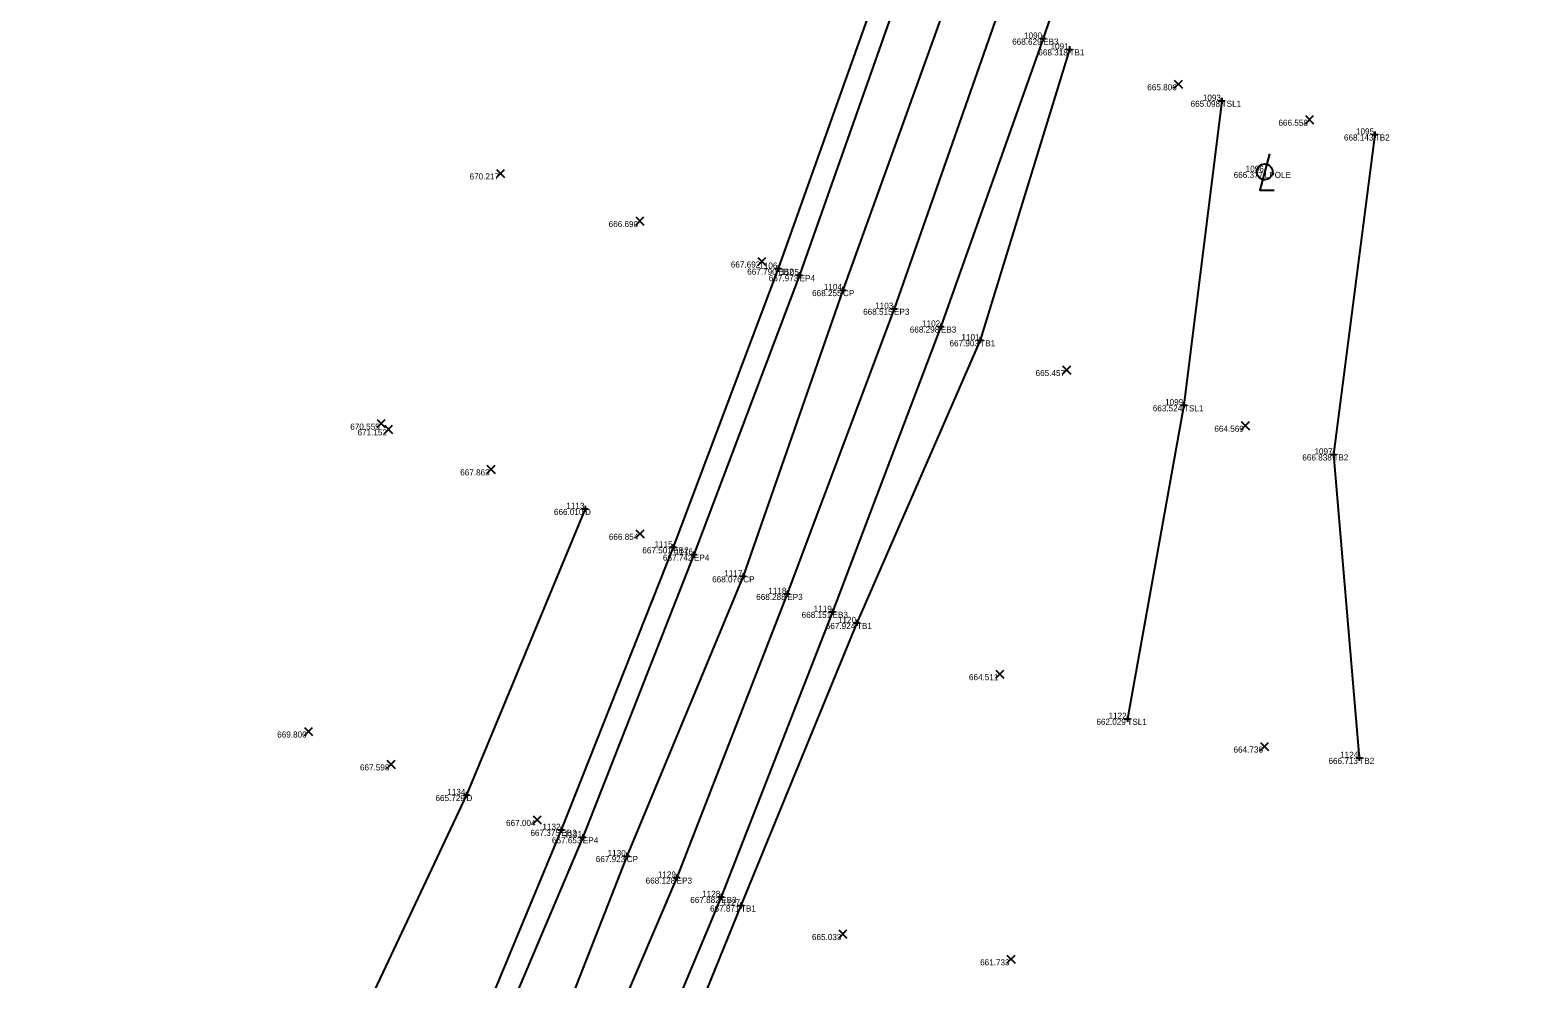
# Model space of a CAD drawing. Extents: x 2197382 to 2204062, y 634117 to 636522.
# Drawn here: x 2203093 to 2203340.5, y 636035.1 to 636190.8 of the extents above; entities that cross this region are included whole.
import ezdxf

# ---------------------------------------------------------------- set-up
doc = ezdxf.new("R2010")
doc.units = 0
for name, color, linetype in [('_CIVIL_CONSTRUCTION', 7, 'Continuous'), ('DR_X_Ditch', 7, 'Continuous'), ('GE_P_Alignment_100_Distances', 7, 'Continuous'), ('GE_X_Alignment', 7, 'Continuous'), ('LT_X_Poles', 7, 'Continuous'), ('PF_P_Grade_Line', 7, 'Continuous'), ('PV_X_COP', 7, 'Continuous'), ('RW_X_CL_100_Curve_Data', 7, 'Continuous'), ('SH_Border', 7, 'Continuous'), ('SH_Cut_Line', 7, 'Continuous'), ('SH_Data', 7, 'Continuous'), ('SV_X_Toe_of_Slope', 7, 'Continuous')]:
    doc.layers.add(name, color=color, linetype=linetype)

msp = doc.modelspace()

# ---------------------------------------------------------------- linework, layer by layer
at = {"layer": '_CIVIL_CONSTRUCTION'}
for p, q in [((2203258.79, 636189.41), (2203259.79, 636189.41)), ((2203259.29, 636189.91), (2203259.29, 636188.91)), ((2203259.29, 636189.41), (2203259.29, 636189.41)), ((2203263.1, 636187.64), (2203264.1, 636187.64)), ((2203263.6, 636188.14), (2203263.6, 636187.14)), ((2203263.6, 636187.64), (2203263.6, 636187.64)), ((2203288.09, 636179.21), (2203289.09, 636179.21)), ((2203288.59, 636179.71), (2203288.59, 636178.71)), ((2203288.59, 636179.21), (2203288.59, 636179.21)), ((2203313.72, 636174.18), (2203313.72, 636173.18)), ((2203313.22, 636173.68), (2203314.22, 636173.68)), ((2203313.72, 636173.68), (2203313.72, 636173.68)), ((2203215.82, 636152.16), (2203215.82, 636151.16)), ((2203215.32, 636151.66), (2203216.32, 636151.66)), ((2203215.82, 636151.66), (2203215.82, 636151.66)), ((2203218.81, 636150.6), (2203219.81, 636150.6)), ((2203219.31, 636151.1), (2203219.31, 636150.1)), ((2203219.31, 636150.6), (2203219.31, 636150.6)), ((2203225.93, 636148.15), (2203226.93, 636148.15)), ((2203226.43, 636148.65), (2203226.43, 636147.65)), ((2203226.43, 636148.15), (2203226.43, 636148.15)), ((2203234.31, 636145.08), (2203235.31, 636145.08)), ((2203234.81, 636145.58), (2203234.81, 636144.58)), ((2203234.81, 636145.08), (2203234.81, 636145.08)), ((2203242, 636142.16), (2203243, 636142.16)), ((2203242.5, 636142.66), (2203242.5, 636141.66)), ((2203242.5, 636142.16), (2203242.5, 636142.16)), ((2203248.47, 636139.91), (2203249.47, 636139.91)), ((2203248.97, 636140.41), (2203248.97, 636139.41)), ((2203248.97, 636139.91), (2203248.97, 636139.91)), ((2203282.4, 636129.75), (2203282.4, 636128.75)), ((2203281.9, 636129.25), (2203282.9, 636129.25)), ((2203282.4, 636129.25), (2203282.4, 636129.25)), ((2203306.43, 636121.18), (2203307.43, 636121.18)), ((2203306.93, 636121.68), (2203306.93, 636120.68)), ((2203306.93, 636121.18), (2203306.93, 636121.18)), ((2203183.6, 636112.24), (2203184.6, 636112.24)), ((2203184.1, 636112.74), (2203184.1, 636111.74)), ((2203184.1, 636112.24), (2203184.1, 636112.24)), ((2203198.08, 636105.93), (2203199.08, 636105.93)), ((2203198.58, 636106.43), (2203198.58, 636105.43)), ((2203198.58, 636105.93), (2203198.58, 636105.93)), ((2203201.46, 636104.73), (2203202.46, 636104.73)), ((2203201.96, 636105.23), (2203201.96, 636104.23)), ((2203201.96, 636104.73), (2203201.96, 636104.73)), ((2203209.56, 636101.18), (2203210.56, 636101.18)), ((2203210.06, 636101.68), (2203210.06, 636100.68)), ((2203210.06, 636101.18), (2203210.06, 636101.18)), ((2203216.79, 636098.29), (2203217.79, 636098.29)), ((2203217.29, 636098.79), (2203217.29, 636097.79)), ((2203217.29, 636098.29), (2203217.29, 636098.29)), ((2203224.23, 636095.35), (2203225.23, 636095.35)), ((2203224.73, 636095.85), (2203224.73, 636094.85)), ((2203224.73, 636095.35), (2203224.73, 636095.35)), ((2203228.23, 636093.53), (2203229.23, 636093.53)), ((2203228.73, 636094.03), (2203228.73, 636093.03)), ((2203228.73, 636093.53), (2203228.73, 636093.53)), ((2203272.61, 636077.8), (2203273.61, 636077.8)), ((2203273.11, 636078.3), (2203273.11, 636077.3)), ((2203273.11, 636077.8), (2203273.11, 636077.8)), ((2203310.68, 636071.39), (2203311.68, 636071.39)), ((2203311.18, 636071.89), (2203311.18, 636070.89)), ((2203311.18, 636071.39), (2203311.18, 636071.39)), ((2203164.13, 636065.3), (2203165.13, 636065.3)), ((2203164.63, 636065.8), (2203164.63, 636064.8)), ((2203164.63, 636065.3), (2203164.63, 636065.3)), ((2203179.7, 636059.59), (2203180.7, 636059.59)), ((2203180.2, 636060.09), (2203180.2, 636059.09)), ((2203180.2, 636059.59), (2203180.2, 636059.59)), ((2203183.23, 636058.36), (2203184.23, 636058.36)), ((2203183.73, 636058.86), (2203183.73, 636057.86)), ((2203183.73, 636058.36), (2203183.73, 636058.36)), ((2203190.43, 636055.28), (2203191.43, 636055.28)), ((2203190.93, 636055.78), (2203190.93, 636054.78)), ((2203190.93, 636055.28), (2203190.93, 636055.28)), ((2203198.64, 636051.74), (2203199.64, 636051.74)), ((2203199.14, 636052.24), (2203199.14, 636051.24)), ((2203199.14, 636051.74), (2203199.14, 636051.74)), ((2203205.94, 636048.57), (2203206.94, 636048.57)), ((2203206.44, 636049.07), (2203206.44, 636048.07)), ((2203206.44, 636048.57), (2203206.44, 636048.57)), ((2203209.19, 636047.17), (2203210.19, 636047.17)), ((2203209.69, 636047.67), (2203209.69, 636046.67)), ((2203209.69, 636047.17), (2203209.69, 636047.17))]:
    msp.add_line(p, q, dxfattribs=at)
at = {"layer": 'DR_X_Ditch'}
msp.add_lwpolyline([(2203184.1, 636112.24), (2203164.63, 636065.3), (2203144.25, 636021.99), (2203126.27, 635973.65), (2203105.52, 635930.12), (2203083.98, 635884.54), (2203067.89, 635850.01), (2203034.81, 635789.04), (2203015.61, 635755.76), (2202991.81, 635713.71), (2202963.02, 635673.98)], dxfattribs=at)
at = {"layer": 'GE_P_Alignment_100_Distances'}
for points in [[(2203324.48, 636507.85), (2203318.62, 636484.14), (2203306.91, 636435.63), (2203294.22, 636387.53), (2203281.02, 636340.01), (2203266.86, 636291.74), (2203251.88, 636244.73), (2203235.99, 636197.91), (2203219.31, 636150.6), (2203201.96, 636104.73), (2203183.73, 636058.36), (2203164.29, 636012.58), (2203144.31, 635966.64), (2203123.63, 635921.48), (2203102.28, 635876.46), (2203085.37, 635841.98), (2203051.94, 635779.64), (2203032.08, 635745.73), (2203005.62, 635703.58), (2202977.57, 635663.01), (2202948.44, 635623.54), (2202917.31, 635585.47), (2202885.13, 635547.53), (2202851.31, 635511.58)], [(2203340.49, 636502.89), (2203334.83, 636480.1), (2203323.13, 636431.59), (2203310.29, 636383.13), (2203297.23, 636335.04), (2203282.66, 636287.13), (2203267.38, 636239.56), (2203251.38, 636192.17), (2203234.81, 636145.08), (2203217.29, 636098.29), (2203199.14, 636051.74), (2203179.44, 636005.69), (2203159.56, 635959.77), (2203137.84, 635914.65), (2203117.45, 635869.06), (2203100.66, 635835.13), (2203066.13, 635771.41), (2203046.09, 635737.06), (2203019.37, 635694.82), (2202991.01, 635653.88), (2202961.19, 635613.48), (2202929.73, 635574.61), (2202897.41, 635536.46), (2202863.17, 635499.96)]]:
    msp.add_lwpolyline(points, dxfattribs=at)
at = {"layer": 'GE_X_Alignment'}
for points in [[(2203321.2, 636508.87), (2203315.42, 636484.99), (2203303.56, 636436.4), (2203290.91, 636388.48), (2203277.67, 636341.19), (2203263.29, 636292.83), (2203248.5, 636245.95), (2203232.65, 636199.01), (2203215.82, 636151.66), (2203198.58, 636105.93), (2203180.2, 636059.59), (2203161.3, 636014.11), (2203141.29, 635968.09), (2203120.26, 635923.09), (2203098.92, 635878.1), (2203081.73, 635843.65), (2203048.56, 635781.48), (2203029.15, 635747.49), (2203002.61, 635705.63), (2202974.64, 635665.31), (2202945.56, 635625.56), (2202914.38, 635588.2), (2202882.41, 635550.01), (2202847.99, 635514.11)], [(2203331.27, 636429.38), (2203318.29, 636380.99), (2203304.79, 636332.88), (2203290.18, 636284.77), (2203275.23, 636236.57), (2203259.29, 636189.41), (2203242.5, 636142.16), (2203224.73, 636095.35), (2203206.44, 636048.57), (2203187.1, 636002.46), (2203167.05, 635956.43), (2203145.71, 635910.9), (2203124.58, 635865.62), (2203107.54, 635831.47), (2203073.07, 635766.88), (2203053.33, 635732.69), (2203026.37, 635690.11), (2202997.51, 635648.24), (2202967.93, 635608.32), (2202935.99, 635569.18), (2202902.86, 635531.15), (2202868.61, 635494.33)]]:
    msp.add_lwpolyline(points, dxfattribs=at)
at = {"layer": 'LT_X_Poles'}
msp.add_lwpolyline([(2203296.44, 636170.49), (2203294.86, 636164.51), (2203297.23, 636164.51)], dxfattribs=at)
msp.add_circle((2203295.65, 636167.54), 1.3, dxfattribs=at)
at = {"layer": 'PF_P_Grade_Line'}
for points in [[(2203263.6, 636187.64), (2203248.97, 636139.91), (2203228.73, 636093.53), (2203209.69, 636047.17), (2203190.81, 636000.71), (2203171.68, 635954.63), (2203151.19, 635908.23), (2203127.58, 635864.5), (2203111.43, 635829.11), (2203075.98, 635764.92), (2203057.74, 635729.87), (2203030.91, 635688.09), (2203003.19, 635643.55), (2202971.04, 635606.63), (2202940.16, 635565.41)], [(2203313.72, 636173.68), (2203306.93, 636121.18), (2203311.18, 636071.39)]]:
    msp.add_lwpolyline(points, dxfattribs=at)
at = {"layer": 'PV_X_COP'}
msp.add_lwpolyline([(2203333.12, 636504.55), (2203327.23, 636481.85), (2203314.64, 636433.62), (2203302.94, 636385.15), (2203289.25, 636336.51), (2203274.73, 636289.23), (2203259.31, 636242.63), (2203243.41, 636195.32), (2203226.43, 636148.15), (2203210.06, 636101.18), (2203190.93, 636055.28), (2203172.74, 636008.76), (2203151.47, 635963.31), (2203132.08, 635917.44), (2203109.53, 635872.8), (2203093.5, 635838.3), (2203058.15, 635776.21), (2203038.88, 635741.65), (2203011.92, 635699.74), (2202984.39, 635657.94), (2202954.68, 635618.56), (2202923.73, 635579.74), (2202891.73, 635541.49), (2202857.33, 635505.37)], dxfattribs=at)
at = {"layer": 'RW_X_CL_100_Curve_Data'}
for p, q in [((2203280.81, 636181.25), (2203282.15, 636182.59)), ((2203280.81, 636182.59), (2203282.15, 636181.25)), ((2203302.34, 636175.43), (2203303.68, 636176.77)), ((2203302.34, 636176.77), (2203303.68, 636175.43)), ((2203169.57, 636166.62), (2203170.9, 636167.95)), ((2203169.57, 636167.95), (2203170.9, 636166.62)), ((2203192.42, 636158.81), (2203193.75, 636160.14)), ((2203192.42, 636160.14), (2203193.75, 636158.81)), ((2203212.43, 636152.17), (2203213.76, 636153.51)), ((2203212.43, 636153.51), (2203213.76, 636152.17)), ((2203262.48, 636134.36), (2203263.81, 636135.7)), ((2203262.48, 636135.7), (2203263.81, 636134.36)), ((2203149.97, 636125.58), (2203151.3, 636126.91)), ((2203149.97, 636126.91), (2203151.3, 636125.58)), ((2203151.16, 636124.63), (2203152.49, 636125.96)), ((2203151.16, 636125.96), (2203152.49, 636124.63)), ((2203291.8, 636125.22), (2203293.14, 636126.56)), ((2203291.8, 636126.56), (2203293.14, 636125.22)), ((2203168, 636118.06), (2203169.34, 636119.4)), ((2203168, 636119.4), (2203169.34, 636118.06)), ((2203192.45, 636107.49), (2203193.78, 636108.82)), ((2203192.45, 636108.82), (2203193.78, 636107.49)), ((2203251.53, 636084.46), (2203252.86, 636085.8)), ((2203251.53, 636085.8), (2203252.86, 636084.46)), ((2203138.02, 636075.05), (2203139.35, 636076.38)), ((2203138.02, 636076.38), (2203139.35, 636075.05)), ((2203294.97, 636072.59), (2203296.3, 636073.92)), ((2203294.97, 636073.92), (2203296.3, 636072.59)), ((2203151.58, 636069.65), (2203152.91, 636070.99)), ((2203151.58, 636070.99), (2203152.91, 636069.65)), ((2203175.59, 636060.55), (2203176.92, 636061.88)), ((2203175.59, 636061.88), (2203176.92, 636060.55)), ((2203225.74, 636041.81), (2203227.07, 636043.14)), ((2203225.74, 636043.14), (2203227.07, 636041.81)), ((2203253.33, 636037.67), (2203254.67, 636039)), ((2203253.33, 636039), (2203254.67, 636037.67))]:
    msp.add_line(p, q, dxfattribs=at)
at = {"layer": 'SV_X_Toe_of_Slope'}
msp.add_lwpolyline([(2203288.59, 636179.21), (2203282.4, 636129.25), (2203273.11, 636077.8)], dxfattribs=at)

# ---------------------------------------------------------------- texts
at = {"layer": 'SH_Border'}
for s, p in [('EB3', (2203259.29, 636188.41)), ('TB1', (2203263.6, 636186.64)), ('TSL1', (2203288.59, 636178.21)), ('TB2', (2203313.72, 636172.68)), ('LPOLE', (2203295.65, 636166.54)), ('EB2', (2203215.82, 636150.66)), ('EP4', (2203219.31, 636149.6)), ('CP', (2203226.43, 636147.15)), ('EP3', (2203234.81, 636144.08)), ('EB3', (2203242.5, 636141.16)), ('TB1', (2203248.97, 636138.91)), ('TSL1', (2203282.4, 636128.25)), ('TB2', (2203306.93, 636120.18)), ('D', (2203184.1, 636111.24)), ('EB2', (2203198.58, 636104.94)), ('EP4', (2203201.96, 636103.73)), ('CP', (2203210.06, 636100.18)), ('EP3', (2203217.29, 636097.29)), ('EB3', (2203224.73, 636094.35)), ('TB1', (2203228.73, 636092.53)), ('TSL1', (2203273.11, 636076.8)), ('TB2', (2203311.18, 636070.39)), ('D', (2203164.63, 636064.3)), ('EB2', (2203180.2, 636058.59)), ('EP4', (2203183.73, 636057.36)), ('CP', (2203190.93, 636054.28)), ('EP3', (2203199.14, 636050.74)), ('EB3', (2203206.44, 636047.57)), ('TB1', (2203209.69, 636046.17))]:
    msp.add_text(s, height=1, dxfattribs=at).set_placement(p)
at = {"layer": 'SH_Cut_Line'}
for s, p in [('1090', (2203256.15, 636189.41)), ('1091', (2203260.5, 636187.64)), ('1093', (2203285.5, 636179.21)), ('1095', (2203310.63, 636173.68)), ('1096', (2203292.53, 636167.54)), ('1106', (2203212.7, 636151.66)), ('1105', (2203216.22, 636150.6)), ('1104', (2203223.29, 636148.15)), ('1103', (2203231.72, 636145.08)), ('1102', (2203239.41, 636142.16)), ('1101', (2203245.87, 636139.91)), ('1099', (2203279.3, 636129.25)), ('1097', (2203303.82, 636121.18)), ('1113', (2203181.02, 636112.24)), ('1115', (2203195.49, 636105.93)), ('1116', (2203198.83, 636104.73)), ('1117', (2203206.95, 636101.18)), ('1118', (2203214.17, 636098.29)), ('1119', (2203221.63, 636095.35)), ('1120', (2203225.6, 636093.53)), ('1122', (2203270.02, 636077.8)), ('1124', (2203308.04, 636071.39)), ('1134', (2203161.49, 636065.3)), ('1132', (2203177.1, 636059.59)), ('1131', (2203180.63, 636058.36)), ('1130', (2203187.79, 636055.28)), ('1129', (2203196.04, 636051.74)), ('1128', (2203203.32, 636048.57)), ('1127', (2203206.58, 636047.17))]:
    msp.add_text(s, height=1, dxfattribs=at).set_placement(p)
at = {"layer": 'SH_Data'}
for s, p in [('668.629', (2203254.2, 636188.41)), ('668.318', (2203258.5, 636186.64)), ('665.806', (2203276.38, 636180.92)), ('665.098', (2203283.49, 636178.21)), ('666.558', (2203297.91, 636175.1)), ('668.143', (2203308.66, 636172.68)), ('670.217', (2203165.14, 636166.29)), ('666.377', (2203290.56, 636166.54)), ('666.690', (2203187.97, 636158.47)), ('667.692', (2203208.02, 636151.84)), ('667.790', (2203210.71, 636150.66)), ('667.973', (2203214.25, 636149.6)), ('668.255', (2203221.36, 636147.15)), ('668.515', (2203229.74, 636144.08)), ('668.298', (2203237.4, 636141.16)), ('667.903', (2203243.91, 636138.91)), ('665.457', (2203258.05, 636134.03)), ('663.524', (2203277.28, 636128.25)), ('670.555', (2203145.56, 636125.24)), ('671.152', (2203146.75, 636124.3)), ('664.569', (2203287.39, 636124.89)), ('666.838', (2203301.83, 636120.18)), ('667.863', (2203163.61, 636117.73)), ('666.010', (2203178.99, 636111.24)), ('666.854', (2203188, 636107.16)), ('667.501', (2203193.5, 636104.94)), ('667.742', (2203196.88, 636103.73)), ('668.076', (2203204.96, 636100.18)), ('668.288', (2203212.19, 636097.29)), ('668.151', (2203219.65, 636094.35)), ('667.924', (2203223.61, 636092.53)), ('664.511', (2203247.11, 636084.13)), ('662.029', (2203268.03, 636076.8)), ('669.800', (2203133.57, 636074.72)), ('664.736', (2203290.53, 636072.25)), ('667.598', (2203147.15, 636069.32)), ('666.713', (2203306.12, 636070.39)), ('665.729', (2203159.54, 636064.3)), ('667.004', (2203171.13, 636060.21)), ('667.375', (2203175.13, 636058.59)), ('667.653', (2203178.66, 636057.36)), ('667.923', (2203185.86, 636054.28)), ('668.128', (2203194.04, 636050.74)), ('667.882', (2203201.37, 636047.57)), ('667.871', (2203204.61, 636046.17)), ('665.033', (2203221.34, 636041.48)), ('661.733', (2203248.94, 636037.33))]:
    msp.add_text(s, height=1, dxfattribs=at).set_placement(p)

doc.saveas('drawing.dxf')
